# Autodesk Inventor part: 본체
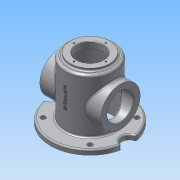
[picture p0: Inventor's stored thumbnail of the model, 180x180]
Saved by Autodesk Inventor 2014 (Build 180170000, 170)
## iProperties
Created: 2018-04
Part Number: 본체
Material: 알루미늄 6061
Document SubType Name: Modeling
Designer: NET
Mass: 1152.46 g
Surface Area: 1202.18 cm^2
Volume: 425.264 cm^3
Density: 2.71 g/cm^3
Appearance: 알루미늄 - 평지
Author: NET
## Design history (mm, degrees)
sketch "스케치2"
  geometry: C1 r 50 at (0, 0); 1 further point
  constraints: 1 centre point, 1 coincident
  dimensions: "d2" = 100 diameter of C1
extrude "돌출1" new body sketch "스케치2" distance "d3" = 128; taper "d4" = 0 deg
hole "구멍1" diameter "d7" = 90; stored, may be unused: countersink angle "d11" = 90 deg, drill point angle "d13" = 0 deg; dims "d5" = 10, "d6" = 10, "d8" = 6, "d9" = 4, "d10" = 2, "d12" = 120
hole "구멍2" diameter "d16" = 54; stored, may be unused: countersink angle "d20" = 90 deg, drill point angle "d22" = 0 deg; dims "d14" = 10, "d15" = 10, "d17" = 6, "d18" = 4, "d19" = 2, "d21" = 120
node "작업 평면1"
sketch "스케치3"
  geometry: C1 r 50 at (0, 0) reference; A1 r 15 centre (-80, 0) between (-78.594, -14.934) and (-78.594, 14.934); A2 r 15 centre (80, 0) between (78.594, 14.934) and (78.594, -14.934); A3 r 80 centre (0, 0) between (-78.594, -14.934) and (78.594, -14.934); A4 r 80 centre (0, 0) between (78.594, 14.934) and (-78.594, 14.934); 1 further point
  constraints: 8 point on circle, 4 centre point, 2 horizontal alignment, 1 coincident
  dimensions: "d25" = 30 diameter of A1; "d27" = 30 diameter of A2; "d28" = 80 radius of A4; "d29" = 80 radius of A3; "d30" = 80 distance of A1.centre point (0, 0); "d31" = 80 distance of A2.centre point (0, 0)
extrude "돌출2" join sketch "스케치3" distance "d32" = 10; taper "d33" = 0 deg
sketch "스케치4"
  geometry: C1 r 27 at (0, 0) reference; C2 r 50 at (0, 0) reference; C3 r 40 at (0, 0)
  constraints: 1 centre point, 1 coincident
  dimensions: "d34" = 80 diameter of C3
extrude "돌출3" join sketch "스케치4" distance "d35" = 5; taper "d36" = 0 deg
node "작업 평면2"
sketch "스케치6"
  geometry: L1 (-14.934, 8)-(-80, 8) reference; C1 r 40 at (0, 68); 1 further point
  constraints: 1 centre point, 1 vertical alignment
  dimensions: "d38" = 80 diameter of C1; "d39" = 60 distance from line of C1.centre L1
extrude "돌출4" join sketch "스케치6" distance "d40" = 124; taper "d41" = 0 deg
hole "구멍3" diameter "d44" = 54; stored, may be unused: countersink angle "d48" = 90 deg, drill point angle "d50" = 0 deg; dims "d45" = 6, "d46" = 4, "d47" = 2, "d49" = 120, "d64" = 10, "d65" = 10
sketch "스케치7"
  geometry: C1 r 45 at (0, 0) reference; C2 r 50 at (0, 0) reference; C3 r 45 at (0, 0)
  constraints: 1 centre point, 1 coincident, 1 concentric
extrude "돌출5" cut sketch "스케치7" distance "d51" = 110.75; taper "d52" = 0 deg
sketch "스케치8"
  geometry: C1 r 27 at (0, 0) reference; 2 further points
  constraints: 1 horizontal alignment
  dimensions: "d53" = 32.5 distance of C1.centre point (32.5, 0)
hole "구멍4" sketch "스케치8" at (32.5, 0) diameter "d54" = 3.242; stored, may be unused: countersink angle "d58" = 90 deg, drill point angle "d60" = 118 deg; dims "d55" = 8, "d56" = 4, "d57" = 2, "d59" = 10
sketch "스케치9"
  geometry: C1 r 27 at (0, 0) reference; 1 further point
  constraints: 1 vertical alignment
  dimensions: "d66" = 32.5 distance of point (0, 32.5) C1.centre
hole "구멍5" sketch "스케치9" at (0, 32.5) diameter "d67" = 3.242; stored, may be unused: countersink angle "d71" = 90 deg, drill point angle "d73" = 118 deg; dims "d68" = 8, "d69" = 4, "d70" = 2, "d72" = 10
fillet "모깎기1" dims "d77" = 5
fillet "모깎기2" dims "d78" = 3
chamfer "모따기1" distance "d79" = 1; stored, may be unused: second distance "d80" = 2, angle "d81" = 45 deg
fillet "모깎기3" dims "d82" = 3
sketch "스케치10" dims "d83" = 135
  geometry: L1 (0, 0)-(-47.73, 47.73); L2 (0, 0)-(0, 95.648); C1 r 53 at (0, 0) reference; 1 further point
  constraints: 4 end point, 2 coincident, 1 vertical, 3 other
  dimensions: "d84" = 45 deg angle of L2 L1
hole "구멍6" sketch "스케치10" at (-47.73, 47.73) diameter "d85" = 10; stored, may be unused: countersink angle "d89" = 90 deg, drill point angle "d91" = 118 deg; dims "d86" = 8, "d87" = 4, "d88" = 2, "d90" = 10
node "작업 평면3"
sketch "스케치11"
  geometry: L1 (77.955, 8)-(-77.955, 8) reference; 2 further points
  constraints: 1 vertical alignment, 1 other
  dimensions: "d95" = 70 distance from line of point (0, 78) L1
feature "엠보싱1" sketch "스케치11" dims "d3" = 128, "d4" = 0, "d96" = 0.5, "d97" = 0
fillet "모깎기4" dims "d98" = 3
node "솔리드1"
pattern_circular "원형 패턴1" dims angle "d62" = 360 deg
mirror "대칭1"
pattern_circular "원형 패턴2" dims angle "d75" = 360 deg
pattern_circular "원형 패턴3" dims angle "d93" = 360 deg
other parameters: "d23" = 8, "d37" = -62
